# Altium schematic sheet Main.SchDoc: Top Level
size A4; Author: J. Garnier; DrawnBy: J. Garnier; SheetNumber: 1; SheetTotal: 8
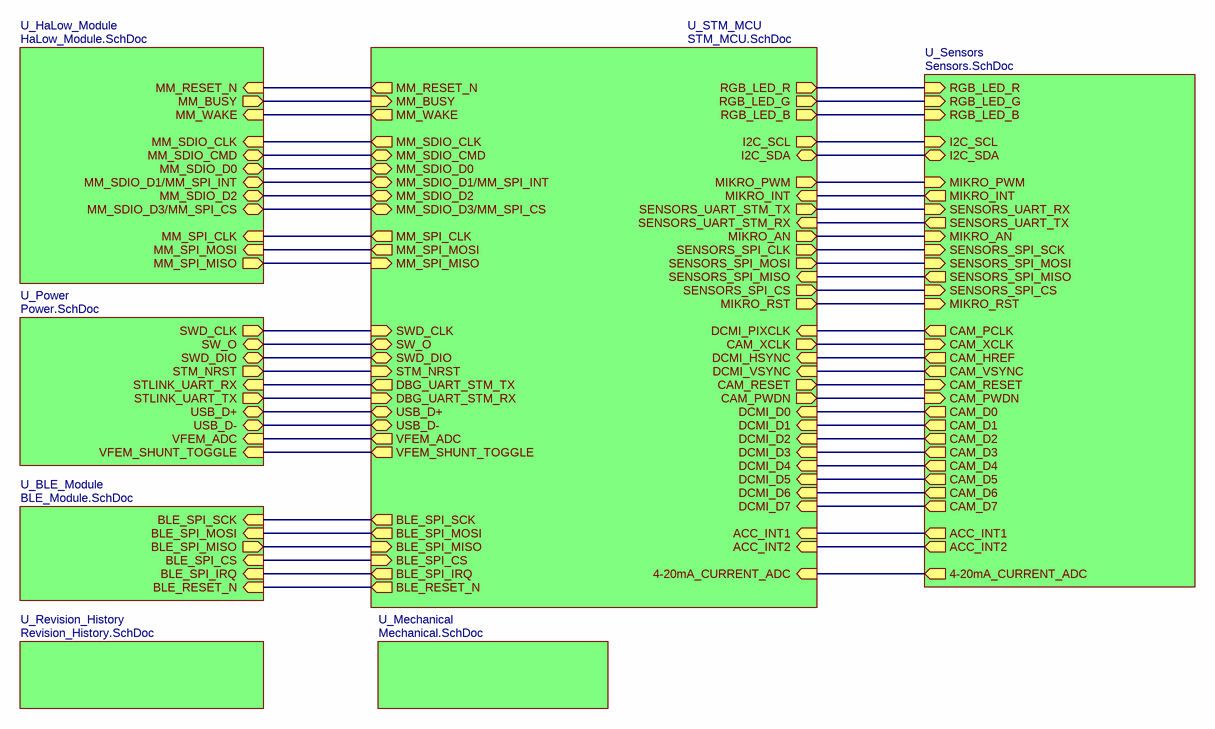
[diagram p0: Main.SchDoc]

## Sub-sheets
U_BLE_Module = BLE_Module.SchDoc: BLE_RESET_N (in), BLE_SPI_IRQ (in), BLE_SPI_CS (in), BLE_SPI_SCK (in), BLE_SPI_MISO (out), BLE_SPI_MOSI (in)
U_HaLow_Module = HaLow_Module.SchDoc: MM_BUSY (out), MM_SDIO_D2 (bidir), MM_SDIO_D0 (bidir), MM_SDIO_CMD (bidir), MM_SDIO_CLK (in), MM_RESET_N (in), MM_WAKE (in), MM_SPI_MISO (out), MM_SPI_MOSI (in), MM_SPI_CLK (in), MM_SDIO_D1/MM_SPI_INT (bidir), MM_SDIO_D3/MM_SPI_CS (bidir)
U_Mechanical = Mechanical.SchDoc: no entries
U_Power = Power.SchDoc: SWD_CLK (out), SWD_DIO (bidir), STLINK_UART_RX (in), STLINK_UART_TX (out), STM_NRST (out), SW_O (bidir), USB_D+ (bidir), USB_D- (bidir), VFEM_ADC (in), VFEM_SHUNT_TOGGLE (in)
U_Revision_History = Revision_History.SchDoc: no entries
U_Sensors = Sensors.SchDoc: ACC_INT1 (out), ACC_INT2 (out), RGB_LED_B (in), RGB_LED_G (in), RGB_LED_R (in), I2C_SCL (in), I2C_SDA (bidir), CAM_HREF (out), CAM_XCLK (in), CAM_D6 (out), CAM_D4 (out), CAM_D2 (out), CAM_D0 (out), CAM_D7 (out), CAM_D5 (out), CAM_D3 (out), CAM_D1 (out), CAM_PWDN (in), CAM_RESET (in), CAM_PCLK (out), CAM_VSYNC (out), MIKRO_INT (out), SENSORS_UART_RX (in), MIKRO_AN (in), SENSORS_SPI_CS (in), SENSORS_SPI_SCK (in), SENSORS_SPI_MISO (out), SENSORS_SPI_MOSI (in), SENSORS_UART_TX (out), MIKRO_PWM (in), MIKRO_RST (in), 4-20mA_CURRENT_ADC (out)
U_STM_MCU = STM_MCU.SchDoc: MM_RESET_N (out), SWD_DIO (bidir), SWD_CLK (in), SENSORS_SPI_MOSI (out), RGB_LED_G (out), RGB_LED_R (out), MM_SPI_CLK (out), RGB_LED_B (out), MM_SDIO_D0 (bidir), MM_BUSY (in), MM_SPI_MISO (in), MM_SPI_MOSI (out), MM_SDIO_CLK (out), MM_SDIO_CMD (bidir), MM_SDIO_D2 (bidir), DCMI_D5 (in), I2C_SCL (out), I2C_SDA (bidir), DCMI_D4 (in), DCMI_D6 (in), DCMI_D7 (in), DCMI_D3 (in), DCMI_D2 (in), DCMI_D1 (in), DCMI_D0 (in), DCMI_PIXCLK (in), DCMI_HSYNC (in), CAM_RESET (out), CAM_PWDN (out), ACC_INT1 (in), ACC_INT2 (in), DBG_UART_STM_RX (in), DBG_UART_STM_TX (out), BLE_RESET_N (out), SENSORS_UART_STM_RX (in), SENSORS_UART_STM_TX (out), DCMI_VSYNC (in), MM_WAKE (out), CAM_XCLK (out), SENSORS_SPI_MISO (in), SENSORS_SPI_CLK (out), SENSORS_SPI_CS (out), MIKRO_INT (in), MIKRO_AN (out), MIKRO_PWM (out), MIKRO_RST (out), 4-20mA_CURRENT_ADC (in), STM_NRST (in), SW_O (bidir), USB_D+ (bidir), USB_D- (bidir), MM_SDIO_D1/MM_SPI_INT (bidir), MM_SDIO_D3/MM_SPI_CS (bidir), BLE_SPI_SCK (out), BLE_SPI_CS (in), BLE_SPI_IRQ (out), BLE_SPI_MISO (in), BLE_SPI_MOSI (out), VFEM_SHUNT_TOGGLE (out), VFEM_ADC (out)

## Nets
(unnamed): sheet U_Power/SWD_CLK, sheet U_STM_MCU/SWD_CLK
(unnamed): sheet U_Power/SWD_DIO, sheet U_STM_MCU/SWD_DIO  [a separate net that carries the same name]
(unnamed): sheet U_Power/STLINK_UART_RX, sheet U_STM_MCU/DBG_UART_STM_TX  [a separate net that carries the same name]
(unnamed): sheet U_Power/STLINK_UART_TX, sheet U_STM_MCU/DBG_UART_STM_RX  [a separate net that carries the same name]
(unnamed): sheet U_Power/STM_NRST, sheet U_STM_MCU/STM_NRST  [a separate net that carries the same name]
(unnamed): sheet U_Power/SW_O, sheet U_STM_MCU/SW_O  [a separate net that carries the same name]
(unnamed): sheet U_Power/USB_D+, sheet U_STM_MCU/USB_D+  [a separate net that carries the same name]
(unnamed): sheet U_Power/USB_D-, sheet U_STM_MCU/USB_D-  [a separate net that carries the same name]
(unnamed): sheet U_Power/VFEM_ADC, sheet U_STM_MCU/VFEM_ADC  [a separate net that carries the same name]
(unnamed): sheet U_Power/VFEM_SHUNT_TOGGLE, sheet U_STM_MCU/VFEM_SHUNT_TOGGLE  [a separate net that carries the same name]
(unnamed): sheet U_STM_MCU/MM_RESET_N, sheet U_HaLow_Module/MM_RESET_N  [a separate net that carries the same name]
(unnamed): sheet U_STM_MCU/SENSORS_SPI_MOSI, sheet U_Sensors/SENSORS_SPI_MOSI  [a separate net that carries the same name]
(unnamed): sheet U_STM_MCU/RGB_LED_G, sheet U_Sensors/RGB_LED_G  [a separate net that carries the same name]
(unnamed): sheet U_STM_MCU/RGB_LED_R, sheet U_Sensors/RGB_LED_R  [a separate net that carries the same name]
(unnamed): sheet U_STM_MCU/MM_SPI_CLK, sheet U_HaLow_Module/MM_SPI_CLK  [a separate net that carries the same name]
(unnamed): sheet U_STM_MCU/RGB_LED_B, sheet U_Sensors/RGB_LED_B  [a separate net that carries the same name]
(unnamed): sheet U_STM_MCU/MM_SDIO_D0, sheet U_HaLow_Module/MM_SDIO_D0  [a separate net that carries the same name]
(unnamed): sheet U_STM_MCU/MM_BUSY, sheet U_HaLow_Module/MM_BUSY  [a separate net that carries the same name]
(unnamed): sheet U_STM_MCU/MM_SPI_MISO, sheet U_HaLow_Module/MM_SPI_MISO  [a separate net that carries the same name]
(unnamed): sheet U_STM_MCU/MM_SPI_MOSI, sheet U_HaLow_Module/MM_SPI_MOSI  [a separate net that carries the same name]
(unnamed): sheet U_STM_MCU/MM_SDIO_CLK, sheet U_HaLow_Module/MM_SDIO_CLK  [a separate net that carries the same name]
(unnamed): sheet U_STM_MCU/MM_SDIO_CMD, sheet U_HaLow_Module/MM_SDIO_CMD  [a separate net that carries the same name]
(unnamed): sheet U_STM_MCU/MM_SDIO_D2, sheet U_HaLow_Module/MM_SDIO_D2  [a separate net that carries the same name]
(unnamed): sheet U_STM_MCU/DCMI_D5, sheet U_Sensors/CAM_D5  [a separate net that carries the same name]
(unnamed): sheet U_STM_MCU/I2C_SCL, sheet U_Sensors/I2C_SCL  [a separate net that carries the same name]
(unnamed): sheet U_STM_MCU/I2C_SDA, sheet U_Sensors/I2C_SDA  [a separate net that carries the same name]
(unnamed): sheet U_STM_MCU/DCMI_D4, sheet U_Sensors/CAM_D4  [a separate net that carries the same name]
(unnamed): sheet U_STM_MCU/DCMI_D6, sheet U_Sensors/CAM_D6  [a separate net that carries the same name]
(unnamed): sheet U_STM_MCU/DCMI_D7, sheet U_Sensors/CAM_D7  [a separate net that carries the same name]
(unnamed): sheet U_STM_MCU/DCMI_D3, sheet U_Sensors/CAM_D3  [a separate net that carries the same name]
(unnamed): sheet U_STM_MCU/DCMI_D2, sheet U_Sensors/CAM_D2  [a separate net that carries the same name]
(unnamed): sheet U_STM_MCU/DCMI_D1, sheet U_Sensors/CAM_D1  [a separate net that carries the same name]
(unnamed): sheet U_STM_MCU/DCMI_D0, sheet U_Sensors/CAM_D0  [a separate net that carries the same name]
(unnamed): sheet U_STM_MCU/DCMI_PIXCLK, sheet U_Sensors/CAM_PCLK  [a separate net that carries the same name]
(unnamed): sheet U_STM_MCU/DCMI_HSYNC, sheet U_Sensors/CAM_HREF  [a separate net that carries the same name]
(unnamed): sheet U_STM_MCU/CAM_RESET, sheet U_Sensors/CAM_RESET  [a separate net that carries the same name]
(unnamed): sheet U_STM_MCU/CAM_PWDN, sheet U_Sensors/CAM_PWDN  [a separate net that carries the same name]
(unnamed): sheet U_STM_MCU/ACC_INT1, sheet U_Sensors/ACC_INT1  [a separate net that carries the same name]
(unnamed): sheet U_STM_MCU/ACC_INT2, sheet U_Sensors/ACC_INT2  [a separate net that carries the same name]
(unnamed): sheet U_STM_MCU/BLE_RESET_N, sheet U_BLE_Module/BLE_RESET_N  [a separate net that carries the same name]
(unnamed): sheet U_STM_MCU/SENSORS_UART_STM_RX, sheet U_Sensors/SENSORS_UART_TX  [a separate net that carries the same name]
(unnamed): sheet U_STM_MCU/SENSORS_UART_STM_TX, sheet U_Sensors/SENSORS_UART_RX  [a separate net that carries the same name]
(unnamed): sheet U_STM_MCU/DCMI_VSYNC, sheet U_Sensors/CAM_VSYNC  [a separate net that carries the same name]
(unnamed): sheet U_STM_MCU/MM_WAKE, sheet U_HaLow_Module/MM_WAKE  [a separate net that carries the same name]
(unnamed): sheet U_STM_MCU/CAM_XCLK, sheet U_Sensors/CAM_XCLK  [a separate net that carries the same name]
(unnamed): sheet U_STM_MCU/SENSORS_SPI_MISO, sheet U_Sensors/SENSORS_SPI_MISO  [a separate net that carries the same name]
(unnamed): sheet U_STM_MCU/SENSORS_SPI_CLK, sheet U_Sensors/SENSORS_SPI_SCK  [a separate net that carries the same name]
(unnamed): sheet U_STM_MCU/SENSORS_SPI_CS, sheet U_Sensors/SENSORS_SPI_CS  [a separate net that carries the same name]
(unnamed): sheet U_STM_MCU/MIKRO_INT, sheet U_Sensors/MIKRO_INT  [a separate net that carries the same name]
(unnamed): sheet U_STM_MCU/MIKRO_AN, sheet U_Sensors/MIKRO_AN  [a separate net that carries the same name]
(unnamed): sheet U_STM_MCU/MIKRO_PWM, sheet U_Sensors/MIKRO_PWM  [a separate net that carries the same name]
(unnamed): sheet U_STM_MCU/MIKRO_RST, sheet U_Sensors/MIKRO_RST  [a separate net that carries the same name]
(unnamed): sheet U_STM_MCU/4-20mA_CURRENT_ADC, sheet U_Sensors/4-20mA_CURRENT_ADC  [a separate net that carries the same name]
(unnamed): sheet U_STM_MCU/MM_SDIO_D1/MM_SPI_INT, sheet U_HaLow_Module/MM_SDIO_D1/MM_SPI_INT  [a separate net that carries the same name]
(unnamed): sheet U_STM_MCU/MM_SDIO_D3/MM_SPI_CS, sheet U_HaLow_Module/MM_SDIO_D3/MM_SPI_CS  [a separate net that carries the same name]
(unnamed): sheet U_STM_MCU/BLE_SPI_SCK, sheet U_BLE_Module/BLE_SPI_SCK  [a separate net that carries the same name]
(unnamed): sheet U_STM_MCU/BLE_SPI_CS, sheet U_BLE_Module/BLE_SPI_CS  [a separate net that carries the same name]
(unnamed): sheet U_STM_MCU/BLE_SPI_IRQ, sheet U_BLE_Module/BLE_SPI_IRQ  [a separate net that carries the same name]
(unnamed): sheet U_STM_MCU/BLE_SPI_MISO, sheet U_BLE_Module/BLE_SPI_MISO  [a separate net that carries the same name]
(unnamed): sheet U_STM_MCU/BLE_SPI_MOSI, sheet U_BLE_Module/BLE_SPI_MOSI  [a separate net that carries the same name]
